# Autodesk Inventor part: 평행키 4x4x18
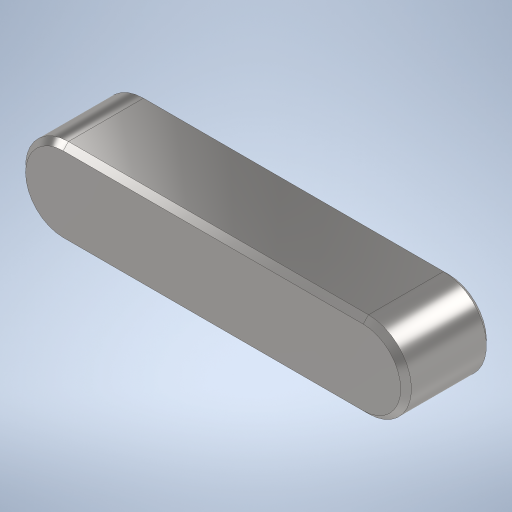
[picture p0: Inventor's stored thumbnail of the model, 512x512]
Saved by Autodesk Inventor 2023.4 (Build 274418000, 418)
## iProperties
Created: 2024-04
Part Number: 평행키 4x4x18
Material: 강철, 연강
Description: 키 및 해당 키홈
Document SubType Name: Modeling
Designer: Edu03
Density: 7.85 g/cm^3
Appearance: 기본값
Author: jhkim
Sending System: Autodesk Inventor 2025
Preprocessor: ST-DEVELOPER v20
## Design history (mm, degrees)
feature "Solid1"
node "솔리드1"
